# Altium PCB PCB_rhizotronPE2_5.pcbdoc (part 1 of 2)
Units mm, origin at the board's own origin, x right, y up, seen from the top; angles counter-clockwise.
Board outline 129.03 x 83.82 mm, 2 copper layers (Top Layer, Bottom Layer); 83 components, 240 nets, 494 pads, 295 vias.
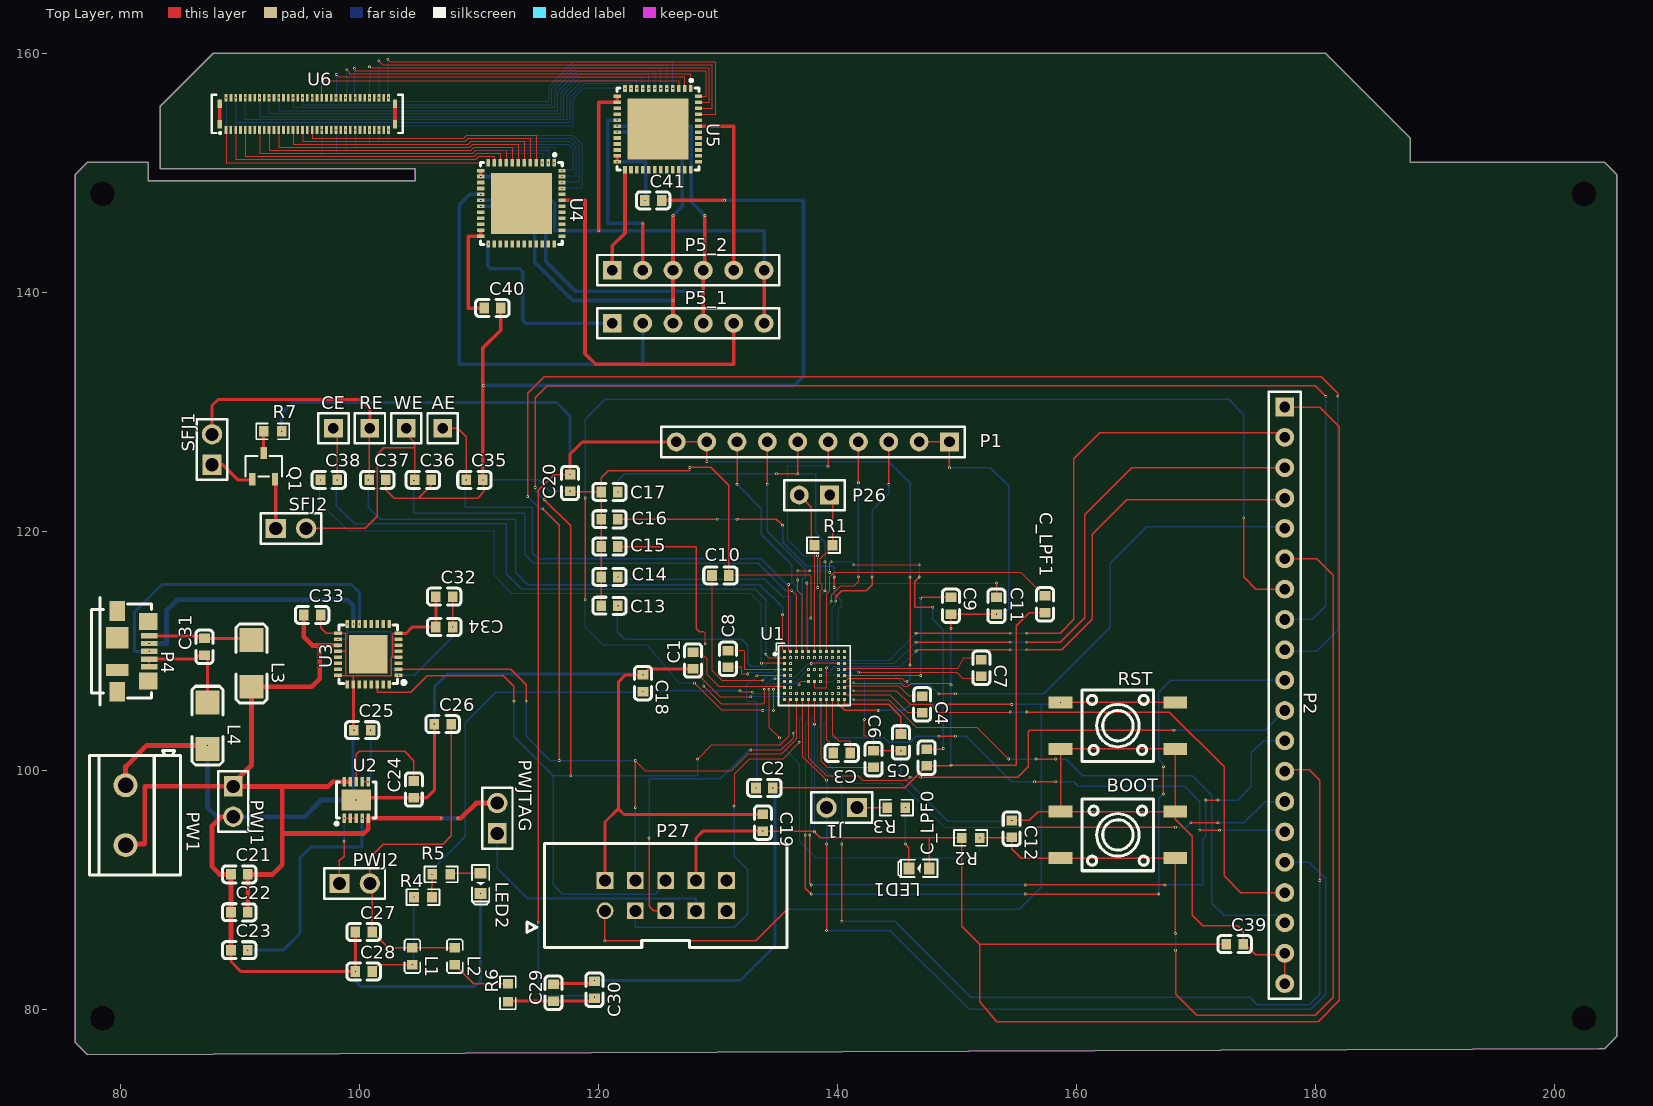
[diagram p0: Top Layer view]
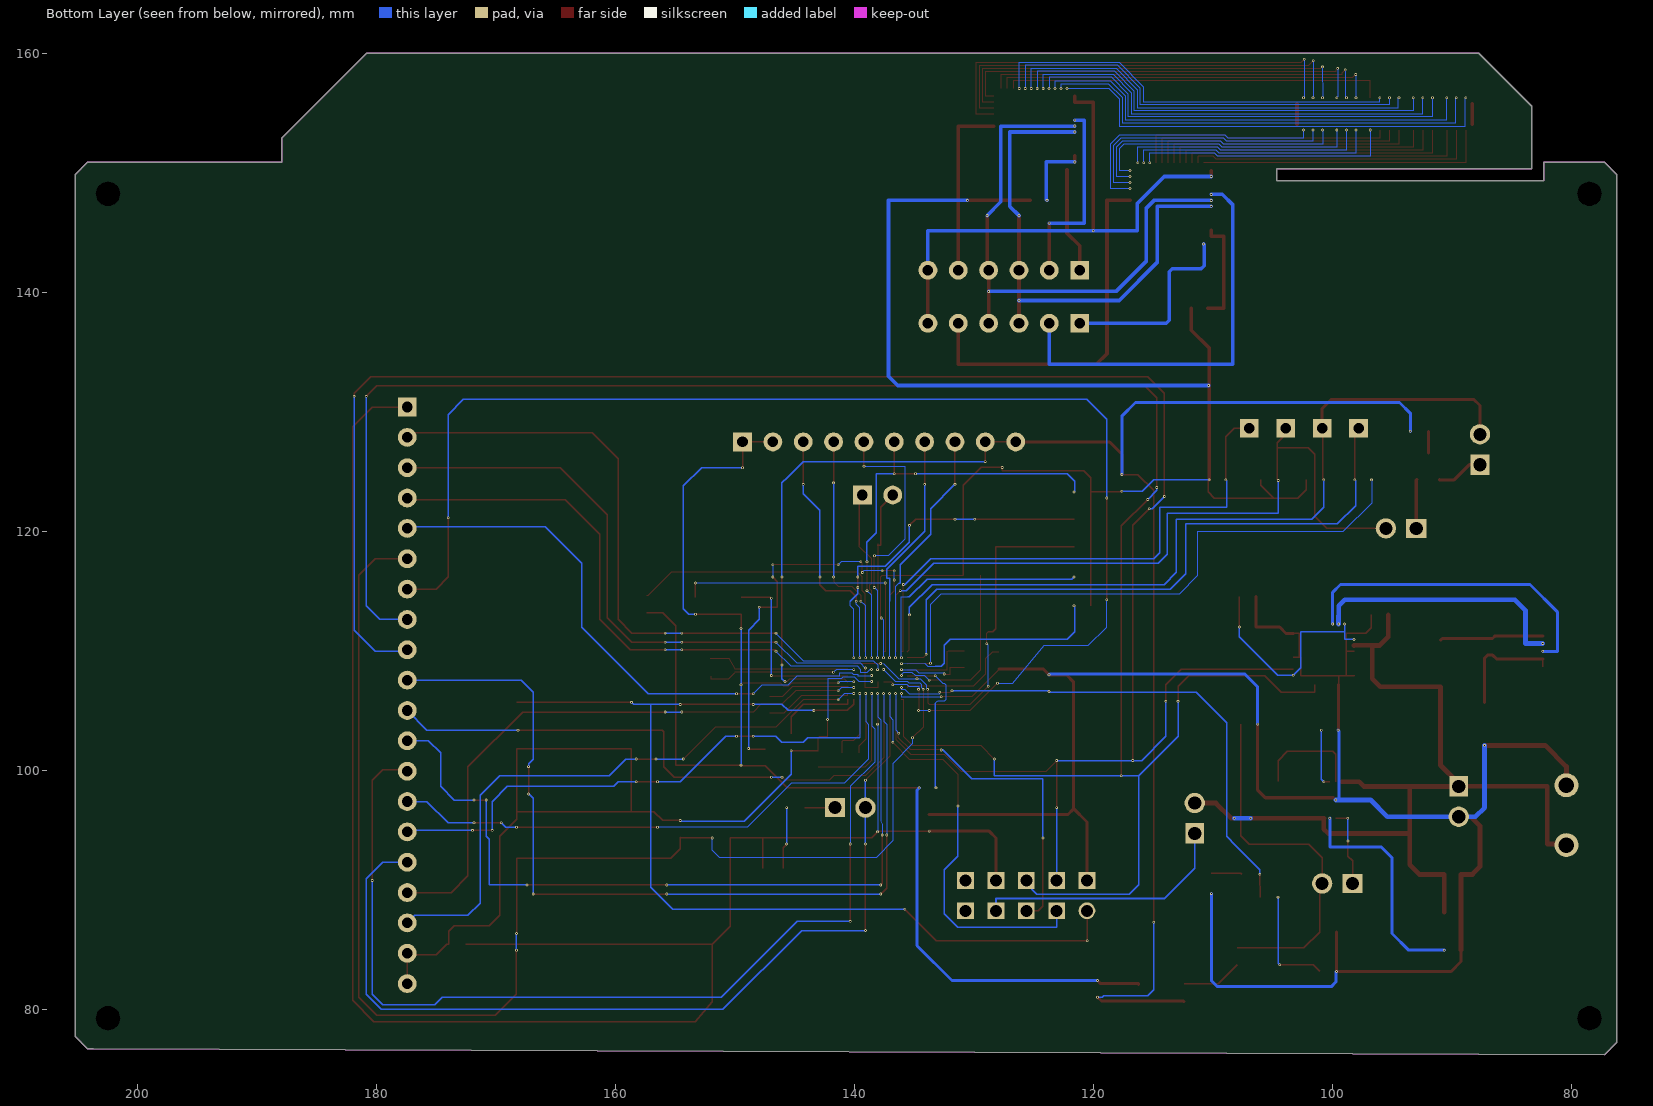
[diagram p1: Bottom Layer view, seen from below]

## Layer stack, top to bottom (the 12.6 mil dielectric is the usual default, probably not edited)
Top Layer: signal copper (thickness not stored)
Dielectric: dielectric 0.32, FR-4, Dk 4.8
Bottom Layer: signal copper (thickness not stored)

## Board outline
82.296,150.876 82.296,149.352 104.648,149.352 104.648,150.368 83.312,150.368 83.312,150.876 83.312,151.242 83.312,151.47 83.312,152.908 83.312,155.575 87.757,160.02 90.424,160.02 180.848,160.02 187.96,152.908 187.96,150.876 204.216,150.876 205.232,149.86 205.232,77.724 204.216,76.708 203.708,76.708 77.216,76.2 76.2,77.216 76.2,149.86 77.216,150.876 82.299,150.876
cut-out: 79.502,79.248 ccw(c78.486,79.248) 77.47,79.248 ccw(c78.486,79.248)
cut-out: 79.502,148.248 ccw(c78.486,148.248) 77.47,148.248 ccw(c78.486,148.248)
cut-out: 203.502,148.248 ccw(c202.486,148.248) 201.47,148.248 ccw(c202.486,148.248)
cut-out: 203.502,79.248 ccw(c202.486,79.248) 201.47,79.248 ccw(c202.486,79.248)

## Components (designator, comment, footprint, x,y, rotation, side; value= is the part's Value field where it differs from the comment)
AE "HDR-M-2.54_1x1" HDR-M-2.54_1X1 106.958,128.627 r270 top
BOOT "K4-6×6_SMD" KEY-SMD_4P-L6.0-W6.0-P3.90-LS10.0 163.473,94.591 r180 top
C1 "0.47uF" C0603 127.913,109.196 r90 top
C2 "0.47uF" C0603 133.882,98.528 r0 top
C3 "0.1uF" C0603 140.359,101.449 r180 top
C4 "0.1uF" C0603 147.09,105.513 r270 top
C5 "0.47uF" C0603 145.312,102.338 r90 top
C6 "0.47uF" C0603 143.026,100.941 r90 top
C7 "0.1uF" C0603 152.043,108.561 r270 top
C8 "0.1uF" C0603 130.834,109.323 r270 top
C9 "0.47uF" C0603 149.503,113.768 r90 top
C10 "0.47uF" C0603 130.199,116.308 r180 top
C11 "4.7uF" C0603 153.313,113.768 r90 top
C12 "0.1uF" C0603 154.583,95.099 r270 top
C13 "0.1uF" C0603 120.928,113.768 r0 top
C14 "0.1uF" C0603 120.928,116.181 r0 top
C15 "0.1uF" C0603 120.928,118.721 r0 top
C16 "0.1uF" C0603 120.928,121.007 r0 top
C17 "0.1uF" C0603 120.928,123.293 r0 top
C18 "0.1uF" C0603 123.722,107.291 r270 top
C19 "0.1uF" C0603 133.755,95.607 r270 top
C20 "0.1uF" C0603 117.626,124.055 r90 top
C21 "0.1uF" C0603 89.94,91.289 r0 top
C22 "10uF" C0603 89.94,88.114 r0 top
C23 "1uF" C0603 89.94,84.939 r0 top
C24 "1uF" C0603 104.545,98.401 r90 top
C25 "1uF" C0603 100.227,103.354 r0 top
C26 "10uF" C0603 106.958,103.862 r0 top
C27 "0.1uF" C0603 100.354,86.463 r0 top
C28 "0.1uF" C0603 100.354,83.161 r0 top
C29 "0.1uF" C0603 116.229,81.383 r90 top
C30 "10uF" C0603 119.658,81.637 r90 top
C31 "0.1uF" C0603 87.019,110.339 r90 top
C32 "0.1uF" C0603 107.085,114.53 r0 top
C33 "0.1uF" C0603 96.036,113.006 r0 top
C34 "0.1uF" C0603 107.085,111.99 r180 top
C35 "0.1uF" C0603 109.625,124.309 r0 top
C36 "0.1uF" C0603 105.307,124.309 r0 top
C37 "0.1uF" C0603 101.497,124.309 r0 top
C38 "0.1uF" C0603 97.433,124.309 r0 top
C39 "0.1uF" C0603 173.252,85.447 r0 top
C40 "0.1uF" C0603 111.125,138.684 r0 top
C41 "0.1uF" C0603 124.587,147.701 r0 top
C_LPF0 "4.7uF" C0603 147.471,101.068 r90 top
C_LPF1 "4.7uF" C0603 157.377,113.895 r90 top
CE "HDR-M-2.54_1x1" HDR-M-2.54_1X1 97.814,128.627 r270 top
J1 "HDR-M-2.54_1x2" HDR-M-2.54_1X2 140.359,96.877 r180 top
L1 "60Ω" L0603 104.418,84.431 r270 top
L2 "60Ω" L0603 107.974,84.431 r270 top
L3 "80Ω" L1806 90.956,108.942 r270 top
L4 "80Ω" L1806 87.273,103.735 r270 top
LED1 "LED-0603_G" LED0603_GREEN 146.836,91.797 r180 top
LED2 "LED-0603_G" LED0603_GREEN 110.133,90.527 r270 top
P1 "HDR-F-2.54_1x10" HDR-F-2.54_1X10 137.946,127.484 r180 top
P2 "HDR-F-2.54_1x20" HDR-F-2.54_1X20 177.443,106.275 r270 top
P4 "Micro B USB 2.0 SMD connector" SD-47346-001 83.082,109.958 r270 top
P5_1 "HDR-F-2.54_1x6" HDR-F-2.54_1X6 126.238,137.414 r0 top
P5_2 "HDR-F-2.54_1x6" HDR-F-2.54_1X6 126.238,141.859 r0 top
P26 "P26" HDR-F-2.54_1X2 138.073,123.039 r180 top
P27 "CONNMOLEX 2X5 Male" JTAG-10PIN-2.54MM-PTH 125.627,89.511 r0 top
PW1 "CONN-TH_2P-P5.00" CONN-TH_2P-P5.00 80.415,96.242 r270 top
PWJ1 "HDR-M-2.54_1x2" HDR-M-2.54_1X2 89.432,97.385 r270 top
PWJ2 "HDR-M-2.54_1x2" HDR-M-2.54_1X2 99.592,90.527 r0 top
PWJTAG "HDR-M-2.54_1x2" HDR-M-2.54_1X2 111.53,95.988 r90 top
Q1 "MMBFJ177" SOT-23-3_L3.0-W1.7-P0.95-LS2.9-BR 91.972,125.452 r270 top
R1 "200" R0603 138.835,118.848 r0 top
R2 "100K" R0603 151.154,94.337 r180 top
R3 "560" R0603 144.931,96.877 r180 top
R4 "2.2" R0603 105.307,89.384 r180 top
R5 "560" R0603 106.831,91.289 r180 top
R6 "2.2" R0603 112.419,81.383 r90 top
R7 "150K" R0603 92.734,128.373 r0 top
RE "HDR-M-2.54_1x1" HDR-M-2.54_1X1 100.862,128.627 r270 top
RST "K4-6×6_SMD" KEY-SMD_4P-L6.0-W6.0-P3.90-LS10.0 163.473,103.735 r0 top
SFJ1 "HDR-M-2.54_1x2" HDR-M-2.54_1X2 87.654,126.849 r90 top
SFJ2 "HDR-M-2.54_1x2" HDR-M-2.54_1X2 94.258,120.245 r0 top
U1 "ADUCM355BCCZ" LGA-72_L6.0-W5.0-TL_ADUCM355BCCZ-RL7 138.073,107.926 r0 top
U2 "ADP7158ACPZ-3.3-R7" LFCSP-10_L3.0-W3.0-P0.50-BL-EP 99.719,97.512 r0 top
U3 "FT232RQ" QFN-32_L5.0-W5.0-P0.50-BL-EP 100.735,109.704 r90 top
U4 "ADG731BCPZ" LFCSP-48_L7.0-W7.0-P0.50-TL-EP5.1 113.538,147.447 r270 top
U5 "ADG731BCPZ" LFCSP-48_L7.0-W7.0-P0.50-TL-EP5.1 124.968,153.67 r270 top
U6 "DF40GB-70DP-0.4V(51)" "HIROSE DF40GB-70DP-0.4V(51)" 95.631,154.94 r0 top
WE "HDR-M-2.54_1x1" HDR-M-2.54_1X1 103.91,128.627 r270 top

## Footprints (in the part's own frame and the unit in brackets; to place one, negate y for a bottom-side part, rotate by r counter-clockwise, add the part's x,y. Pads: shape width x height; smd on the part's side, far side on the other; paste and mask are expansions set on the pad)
C0603 [mm]
  rect 0.8x0.9 smd paste+0 mask+0.051: 1(-0.7,0) 2(0.7,0)
  silkscreen extent -1.41,-0.71 1.39,0.72
CONN-TH_2P-P5.00 [mm]
  round 2 hole 1.3 paste+0 mask+0.051: 1(-2.504,0) 2(2.504,0)
  silkscreen extent -5.4,-3 5,4.6
HDR-F-2.54_1X2 [mil]
  rect 62x62 hole 35 paste+0 mask+2: 1(-50,0)
  round 62 hole 35 paste+0 mask+2: 2(50,0)
  silkscreen extent -100,-49 100,50
HDR-F-2.54_1X6 [mil]
  rect 62x62 hole 35 paste+0 mask+2: 1(-200,0)
  round 62 hole 35 paste+0 mask+2: 2(-100,0) 3(0,0) 4(100,0) 5(200,0) 6(300,0)
  silkscreen extent -250,-50 350,50
HDR-F-2.54_1X10 [mil]
  rect 62x62 hole 35 paste+0 mask+2: 1(-450,0)
  round 62 hole 35 paste+0 mask+2: 2(-350,0) 3(-250,0) 4(-150,0) 5(-50,0) 6(50,0) 7(150,0) 8(250,0) 9(350,0) 10(450,0)
  silkscreen extent -500,-50 500,50
HDR-F-2.54_1X20 [mil]
  rect 62x62 hole 35 paste+0 mask+2: 1(-950,0)
  round 62 hole 35 paste+0 mask+2: 2(-850,0) 3(-750,0) 4(-650,0) 5(-550,0) 6(-450,0) 7(-350,0) 8(-250,0) 9(-150,0) 10(-50,0) 11(50,0) 12(150,0) 13(250,0) 14(350,0) 15(450,0) 16(550,0) 17(650,0) 18(750,0) 19(850,0) 20(950,0)
  silkscreen extent -1000,-53 1000,53
HDR-M-2.54_1X1 [mil]
  rect 62x62 hole 35 paste+0 mask+2: 1(0,0)
  silkscreen extent -50,-50 50,50
HDR-M-2.54_1X2 [mm]
  rect 1.7x1.575 hole 1.1 paste+0 mask+0.051: 1(-1.27,0)
  round 1.7 hole 1.1 paste+0 mask+0.051: 2(1.27,0)
  silkscreen extent -2.54,-1.27 2.54,1.27
"HIROSE DF40GB-70DP-0.4V(51)" [mm]
  rect 0.23x0.66 smd paste+0 mask+0.051: 1(-6.8,-1.355) 2(-6.8,1.355) 3(-6.401,-1.355) 4(-6.4,1.355) 5(-6,-1.355) 6(-6,1.355) 7(-5.6,-1.355) 8(-5.6,1.355) 9(-5.2,-1.355) 10(-5.2,1.355) 11(-4.8,-1.355) 12(-4.8,1.355) 13(-4.4,-1.355) 14(-4.4,1.355) 15(-4,-1.355) 16(-4,1.355) 17(-3.6,-1.355) 18(-3.6,1.355) 19(-3.2,-1.355) 20(-3.2,1.355) 21(-2.8,-1.355) 22(-2.8,1.355) 23(-2.4,-1.355) 24(-2.4,1.355) 25(-2,-1.355) 26(-2,1.355) 27(-1.6,-1.355) 28(-1.6,1.355) 29(-1.2,-1.355) 30(-1.2,1.355) 31(-0.8,-1.355) 32(-0.8,1.355) 33(-0.4,-1.355) 34(-0.4,1.355) 35(0,-1.355) 36(0,1.355) 37(0.4,-1.355) 38(0.4,1.355) 39(0.8,-1.355) 40(0.8,1.355) 41(1.2,-1.355) 42(1.2,1.355) 43(1.6,-1.355) 44(1.6,1.355) 45(2,-1.355) 46(2,1.355) 47(2.4,-1.355) 48(2.4,1.355) 49(2.8,-1.355) 50(2.8,1.355) 51(3.2,-1.355) 52(3.2,1.355) 53(3.6,-1.355) 54(3.6,1.355) 55(4,-1.355) 56(4,1.355) 57(4.4,-1.355) 58(4.4,1.355) 59(4.8,-1.355) 60(4.8,1.355) 61(5.2,-1.355) 62(5.2,1.355) 63(5.6,-1.355) 64(5.6,1.355) 65(6,-1.355) 66(6,1.355) 67(6.4,-1.355) 68(6.4,1.355) 69(6.8,-1.355) 70(6.8,1.355)
  rect 0.35x0.7 smd paste+0 mask+0.051: 71(7.335,-0.86) 72(7.335,0.86) 73(-7.335,-0.86) SHLD(-7.335,0.86)
  silkscreen extent -8,-1.7 8,1.6
JTAG-10PIN-2.54MM-PTH [mm]
  round 1.4 hole 1.001 paste+0 mask+0.051: 1(-5.08,-1.27)
  rect 1.4x1.4 hole 1.001 paste+0 mask+0.051: 2(-5.08,1.27) 3(-2.54,-1.27) 4(-2.54,1.27) 5(0,-1.27) 6(0,1.27) 7(2.54,-1.27) 8(2.54,1.27) 9(5.08,-1.27) 10(5.08,1.27)
  silkscreen extent -11.61,-4.34 10.13,4.34
KEY-SMD_4P-L6.0-W6.0-P3.90-LS10.0 [mm]
  rect 2x1 smd paste+0 mask+0.051: 1(-4.8,1.95) 2(4.8,1.95) 3(-4.8,-1.95) 4(4.8,-1.95)
  silkscreen extent -3,-3 3,3
L0603 [mm]
  rect 0.8x0.864 smd paste-100 mask+0.051: 1(-0.7,0) 2(0.7,0)
  silkscreen extent -1.42,-0.65 1.41,0.67
L1806 [mm]
  rect 2x2 smd paste+0 mask+0.051: 1(-1.95,0) 2(1.95,0)
  silkscreen extent -3.3,-1.3 3.3,1.3
LED0603_GREEN [mm]
  rect 0.9x1 smd paste+0 mask+0.051: 1(-0.85,0) 2(0.85,0)
  silkscreen extent -1.54,-0.73 1.75,0.73
LFCSP-10_L3.0-W3.0-P0.50-BL-EP [mm]
  rect 0.3x0.8 smd paste+0 mask+0.051: 1(-1,-1.524) 2(-0.5,-1.524) 3(0,-1.524) 4(0.5,-1.524) 5(1,-1.524) 6(1,1.524) 7(0.5,1.524) 8(0,1.524) 9(-0.5,1.524) 10(-1,1.524)
  rect 2.5x1.75 smd paste+0 mask+0.051: 11(0,0)
  silkscreen extent -1.77,-2.11 1.65,1.52
LFCSP-48_L7.0-W7.0-P0.50-TL-EP5.1 [mm]
  rect 0.6x0.3 smd paste-100 mask+0.051: 1(-3.4,2.75) 2(-3.4,2.25) 3(-3.4,1.75) 4(-3.4,1.25) 5(-3.4,0.75) 6(-3.4,0.25) 7(-3.4,-0.25) 8(-3.4,-0.75) 9(-3.4,-1.25) 10(-3.4,-1.75) 11(-3.4,-2.25) 12(-3.4,-2.75) 25(3.4,-2.75) 26(3.4,-2.25) 27(3.4,-1.75) 28(3.4,-1.25) 29(3.4,-0.75) 30(3.4,-0.25) 31(3.4,0.25) 32(3.4,0.75) 33(3.4,1.25) 34(3.4,1.75) 35(3.4,2.25) 36(3.4,2.75)
  rect 0.3x0.6 smd paste-100 mask+0.051: 13(-2.75,-3.4) 14(-2.25,-3.4) 15(-1.75,-3.4) 16(-1.25,-3.4) 17(-0.75,-3.4) 18(-0.25,-3.4) 19(0.25,-3.4) 20(0.75,-3.4) 21(1.25,-3.4) 22(1.75,-3.4) 23(2.25,-3.4) 24(2.75,-3.4) 37(2.75,3.4) 38(2.25,3.4) 39(1.75,3.4) 40(1.25,3.4) 41(0.75,3.4) 42(0.25,3.4) 43(-0.25,3.4) 44(-0.75,3.4) 45(-1.25,3.4) 46(-1.75,3.4) 47(-2.25,3.4) 48(-2.75,3.4)
  rect 5.1x5.1 smd paste-100 mask+0.051: 49(0,0)
  silkscreen extent -4.19,-3.43 3.43,3.43
LGA-72_L6.0-W5.0-TL_ADUCM355BCCZ-RL7 [mm]
  rect 0.25x0.25 smd paste+0 mask+0.051: A1(-2.5,2) A2(-2,2) A3(-1.5,2) A4(-1,2) A5(-0.5,2) A6(0,2) A7(0.5,2) A8(1,2) A9(1.5,2) A10(2,2) A11(2.5,2) B1(-2.5,1.5) B2(-2,1.5) B3(-1.5,1.5) B4(-1,1.5) B5(-0.5,1.5) B6(0,1.5) B7(0.5,1.5) B8(1,1.5) B9(1.5,1.5) B10(2,1.5) B11(2.5,1.5) C1(-2.5,1) C2(-2,1) C10(2,1) C11(2.5,1) D1(-2.5,0.5) D2(-2,0.5) D5(-0.5,0.5) D6(0,0.5) D7(0.5,0.5) D10(2,0.5) D11(2.5,0.5) E1(-2.5,0) E2(-2,0) E5(-0.5,0) E7(0.5,0) E10(2,0) E11(2.5,0) F1(-2.5,-0.5) F2(-2,-0.5) F5(-0.5,-0.5) F6(0,-0.5) F7(0.5,-0.5) F10(2,-0.5) F11(2.5,-0.5) G1(-2.5,-1) G2(-2,-1) G10(2,-1) G11(2.5,-1) H1(-2.5,-1.5) H2(-2,-1.5) H3(-1.5,-1.5) H4(-1,-1.5) H5(-0.5,-1.5) H6(0,-1.5) H7(0.5,-1.5) H8(1,-1.5) H9(1.5,-1.5) H10(2,-1.5) H11(2.5,-1.5) J1(-2.5,-2) J2(-2,-2) J3(-1.5,-2) J4(-1,-2) J5(-0.5,-2) J6(0,-2) J7(0.5,-2) J8(1,-2) J9(1.5,-2) J10(2,-2) J11(2.5,-2)
  silkscreen extent -3.4,-2.5 3,2.7
QFN-32_L5.0-W5.0-P0.50-BL-EP [mil]
  rect 11.8x26 smd paste-3937 mask+1.97: 1(-68.9,-100) 2(-49.21,-100) 3(-29.53,-100) 4(-9.84,-100) 5(9.84,-100) 6(29.53,-100) 7(49.21,-100) 8(68.9,-100) 17(68.9,100) 18(49.21,100) 19(29.53,100) 20(9.84,100) 21(-9.84,100) 22(-29.53,100) 23(-49.21,100) 24(-68.9,100)
  rect 26x11.8 smd paste-3937 mask+1.97: 9(100,-68.9) 10(100,-49.21) 11(100,-29.53) 12(100,-9.84) 13(100,9.84) 14(100,29.53) 15(100,49.21) 16(100,68.9) 25(-100,68.9) 26(-100,49.21) 27(-100,29.53) 28(-100,9.84) 29(-100,-9.84) 30(-100,-29.53) 31(-100,-49.21) 32(-100,-68.9)
  rect 126x126 smd paste-3937 mask+1.97: 33(0,0)
  silkscreen extent -99,-123 96,96
R0603 [mm]
  rect 0.806x0.864 smd paste-100 mask+0.051: 1(-0.753,0) 2(0.753,0)
  silkscreen extent -1.39,-0.66 1.39,0.66
SD-47346-001 [mm]
  rect 0.45x1.38 smd paste+0 mask+0.102: 1(-1.3,-0.69) 2(-0.65,-0.69) 3(0,-0.69) 4(0.65,-0.69) 5(1.3,-0.69)
  rect 1.425x1.55 smd paste+0 mask+0.102: 6(-2.488,-0.775) GND(2.488,-0.775)
  rect 1.65x1.3 smd paste+0 mask+0.102: 7(-3.375,-3.35) 10(3.375,-3.35)
  rect 1.8x1.9 smd paste+0 mask+0.102: 8(-1.15,-3.35)
  rect 1x1.9 smd paste+0 mask+0.102: 9(1.55,-3.35)
  silkscreen extent -4.49,-5.5 4.49,-0.5
SOT-23-3_L3.0-W1.7-P0.95-LS2.9-BR [mm]
  rect 1.037x0.532 smd paste+0 mask+0.051: 1(1.101,-0.95) 2(1.101,0.95) 3(-1.101,0)
  silkscreen extent -0.86,-1.53 0.86,1.53

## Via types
v1: diameter 0.225, hole 0.1, Top Layer to Bottom Layer, tented both sides, 295 vias

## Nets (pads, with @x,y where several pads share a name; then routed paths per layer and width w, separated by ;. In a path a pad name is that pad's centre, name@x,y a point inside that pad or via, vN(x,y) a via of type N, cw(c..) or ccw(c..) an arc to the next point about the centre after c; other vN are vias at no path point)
3V3VOUT: C32.2 C34.1 U3.1 U3.16 U3.18 | length 18.8
  Top Layer w0.125: C34.1@107.785,111.99 C32.2@107.785,114.53
  Bottom Layer w0.125: v1(98.195,110.954) 98.957,110.954 98.957,112.216 v1@98.985,112.244 ; 98.957,111.584 102.64,111.584 102.64,108.589 103.275,107.954 104.573,107.954 107.786,111.167 v1@107.786,111.99
  other v1: 103.275,107.954 107.785,111.99 98.985,112.244
5VUSB: C21.2 C22.2 C33.1 L3.2 PW1.2 PWJ1.1 PWJTAG.2 U2.5 U2.9 U2.10 U3.19 | length 79.4
  Top Layer w0.4: PW1.2@80.415,93.737 80.506,93.829 82.03,93.829 82.03,98.655 ; 82.066,98.655 82.03,98.655 ; PWJ1.1@89.432,98.655 97.384,98.654 97.765,99.035 U2.10@98.719,99.036 ; C22.2@90.64,88.114 C21.2@90.64,91.289 92.734,91.289 93.537,92.092 93.537,98.655 ; L3.2@90.956,106.991 95.99,106.991 96.671,107.672 96.671,109.958 96.671,110.466 U3.19@98.195,110.453 ; L3.2@90.956,106.992 90.956,100.433 89.432,98.909 PWJ1.1@89.432,98.655 82.03,98.655 ; 93.536,94.464 93.536,94.718 100.354,94.718 100.72,95.084 U2.5@100.719,95.988 ; C33.1@95.335,113.006 95.335,111.162 96.046,110.453 96.671,110.453 ; U2.10@98.719,99.036 U2.9@99.219,99.036 ; U2.5@100.719,95.988 v1@106.831,95.988 ; v1@108.228,95.988 108.482,95.988 109.752,97.258 PWJTAG.2@111.53,97.258
  Bottom Layer w0.4: v1@106.831,95.988 v1@108.228,95.988
  other v1: 106.831,95.988 108.228,95.988
AFEDIE_GPIO0: P2.17 U1.G10 | length 49.8
  Top Layer w0.1: v1(141.375,106.656) 144.931,106.656 146.074,105.513 147.852,105.513 148.487,104.878 v1@154.456,104.878
  Top Layer w0.125: v1@155.853,104.878 167.791,104.878 172.363,100.306 172.363,91.162 173.76,89.765 P2.17@177.443,89.765
  Bottom Layer w0.1: v1(140.073,106.926) 141.104,106.926 v1(141.375,106.656)
  Bottom Layer w0.125: v1@154.456,104.878 v1@155.853,104.878
  other v1: 154.456,104.878 155.853,104.878
AFEDIE_GPIO1: P2.18 U1.H10 | length 50.6
  Top Layer w0.1: v1(141.375,105.894) 144.296,105.894 146.582,103.608 151.662,103.608 v1@154.329,100.941
  Top Layer w0.125: v1@156.615,100.941 v1@158.266,100.941
  Bottom Layer w0.1: v1(140.073,106.426) 140.842,106.426 v1(141.375,105.894)
  Bottom Layer w0.125: v1@154.329,100.941 v1@156.615,100.941 ; v1@158.266,100.941 159.155,100.941 160.552,99.544 169.696,99.544 171.347,97.893 171.347,88.876 172.363,87.86 176.808,87.86 P2.18@177.443,87.225
  other v1: 154.329,100.941 156.615,100.941 158.266,100.941
AGND: C2.2 C9.1 C10.1 C11.1 C13.1 C14.1 C15.1 C16.1 C17.1 C20.1 C29.2 C30.2 C35.2 C36.2 C37.2 C40.2 C41.2 C_LPF0.1 C_LPF1.1 P1.1 P1.2 U1.B5 U1.F10 | length 252.5
  Top Layer w0.1: C10.1@130.899,116.308 137.692,116.308 137.819,116.181 137.819,112.81 v1@137.76,112.752 ; v1@141.375,107.291 145.312,107.291 145.566,107.037 145.926,107.037 146.18,107.291 149.503,107.291 v1@149.503,107.164
  Top Layer w0.125: C37.2@102.197,124.309 102.197,123.482 102.894,122.785 104.926,122.785 ; C36.2@106.007,124.309 106.007,123.866 104.926,122.785 ; C35.2@110.325,124.309 110.387,124.309 110.387,123.293 109.879,122.785 104.926,122.785 ; v1(117.626,123.355) 117.688,123.293 C17.1@120.228,123.293 ; C13.1@120.228,113.768 C14.1@120.228,116.181 C15.1@120.228,118.721 C16.1@120.228,121.007 C17.1@120.228,123.293 ; C10.1@130.899,116.308 130.899,123.863 129.413,125.349 v1(127.635,125.349) 127.635,125.071 120.801,125.071 120.228,124.498 C17.1@120.228,123.293 ; C2.2@134.582,98.528 145.631,98.528 C_LPF0.1@147.471,100.368 149.438,100.368 149.503,100.433 154.964,100.433 154.964,112.117 156.042,113.195 C_LPF1.1@157.377,113.195 ; P1.2@146.836,127.484 P1.1@149.376,127.484 v1@149.376,125.325 ; v1(149.503,111.863) C9.1@149.503,113.068 v1(153.313,113.068)
  Top Layer w0.254: C29.2@116.229,82.083 116.229,82.145 119.404,82.145 C30.2@119.658,82.399
  Top Layer w0.3: C35.2@110.325,124.309 110.325,135.344 111.825,136.844 C40.2@111.825,138.684 ; C41.2@125.287,147.701 v1(130.556,147.701)
  Bottom Layer w0.1: v1(137.573,109.426) 137.573,112.563 v1(137.762,112.752) ; v1@140.073,107.426 141.239,107.426 v1@141.375,107.291
  Bottom Layer w0.125: v1@110.325,124.309 114.959,124.309 115.913,123.355 v1(117.626,123.355) ; v1@149.376,125.325 152.805,125.325 154.329,123.801 154.329,113.514 153.883,113.068 v1(153.313,113.068) ; v1@149.503,100.433 149.503,107.164 v1(149.503,111.863)
  Bottom Layer w0.254: v1@119.658,82.399 131.85,82.399 134.771,85.32 134.771,98.339 v1@134.582,98.528
  Bottom Layer w0.3: v1(110.363,132.207) 136.398,132.207 137.16,132.969 137.16,147.701 132.334,147.701 v1(130.556,147.701)
  other v1: 119.658,82.399 134.582,98.528 149.503,100.433 149.503,107.164 141.375,107.321 140.073,107.416 110.325,124.309 149.376,125.325
AIN0: P1.3 U1.B9 | length 21.2
  Top Layer w0.125: v1@139.851,114.149 139.851,114.53 140.359,115.038 142.391,115.038 142.899,115.546 v1@142.899,116.181 ; v1@144.296,123.928 P1.3@144.296,127.484
  Bottom Layer w0.1: v1(139.573,109.426) 139.573,113.617 139.851,113.895 v1@139.851,114.149
  Bottom Layer w0.125: v1@142.899,116.181 142.899,121.769 144.296,123.166 v1@144.296,123.928
  other v1: 139.851,114.149 142.899,116.181 144.296,123.928
AIN1: P1.4 U1.B8 | length 19.8
  Top Layer w0.1: v1@139.47,114.149 139.47,114.657 140.232,115.419 141.375,115.419 141.756,115.8 v1@141.756,116.181
  Top Layer w0.125: v1@141.756,124.055 P1.4@141.756,127.484
  Bottom Layer w0.1: v1(139.073,109.426) 139.073,113.752 v1@139.47,114.149
  Bottom Layer w0.125: v1@141.756,116.181 v1@141.756,124.055
  other v1: 139.47,114.149 141.756,116.181 141.756,124.055
AIN2: P1.5 U1.B6 | length 23.3
  Top Layer w0.1: v1@138.334,117.959 v1(138.347,115.292)
  Top Layer w0.125: v1@139.216,125.452 P1.5@139.216,127.484
  Bottom Layer w0.1: v1(138.073,109.426) 138.073,115.038 v1@138.327,115.292 ; v1@138.327,117.959 137.184,117.959 135.787,119.356 135.787,120.224 135.787,125.452 v1@139.216,125.452
  other v1: 138.336,117.959 139.216,125.452
AIN3: C17.2 P1.6 U1.B7 | length 36.4
  Top Layer w0.1: v1(138.962,115.038) v1(138.962,117.451)
  Top Layer w0.125: v1@134.898,124.817 136.676,124.817 P1.6@136.676,127.484
  Bottom Layer w0.1: v1(138.573,109.426) 138.573,114.649 v1(138.962,115.038)
  Bottom Layer w0.125: v1@121.629,123.293 121.563,123.293 121.563,124.182 122.198,124.817 v1@134.898,124.817 ; v1@136.676,124.817 138.2,124.817 138.2,119.864 138.962,119.102 v1(138.962,117.451)
  other v1: 121.628,123.293 134.898,124.817 136.676,124.817
AIN5: P1.7 U1.B4 | length 19.6
  Top Layer w0.125: v1@134.136,123.928 P1.7@134.136,127.484
  Bottom Layer w0.1: v1@137.072,109.427 137.072,114.149
  Bottom Layer w0.125: v1@134.136,123.928 134.136,119.991 137.311,116.816 137.311,116.054 137.057,116.054 137.057,114.149
  other v1: 137.073,109.426 134.136,123.928
AIN6: P1.8 U1.B3 | length 20.2
  Top Layer w0.125: v1@131.596,123.928 P1.8@131.596,127.484
  Bottom Layer w0.1: 136.295,115.673 136.573,115.395 v1(136.573,109.426)
  Bottom Layer w0.125: v1@131.596,123.928 133.628,121.896 133.628,119.737 136.168,117.197 136.168,115.673 136.295,115.673
  other v1: 131.596,123.928
AVDD: C20.2 C29.1 C30.1 P1.9 P1.10 R6.1 R7.2 U1.F11 | length 144
  Top Layer w0.1: U1.F11@140.573,107.426 140.621,107.426 140.867,107.672 145.439,107.672 145.683,107.427 v1(145.82,107.427)
  Top Layer w0.125: v1@114.959,87.225 114.959,123.42 116.294,124.755 v1(117.626,124.755) ; P1.10@126.516,127.484 P1.9@129.056,127.484 v1@129.056,125.833 ; v1@146.074,108.815 v1@146.074,116.181
  Top Layer w0.254: R6.1@112.419,80.629 112.472,80.683 C29.1@116.229,80.683 119.339,80.683 C30.1@119.658,81.002 ; v1(117.626,124.755) 117.626,126.468 118.642,127.484 P1.10@126.516,127.484
  Bottom Layer w0.125: v1(114.959,87.276) 114.959,81.637 115.467,81.129 119.15,81.129 119.277,81.002 v1@119.658,81.002 ; v1@129.056,125.833 144.296,125.833 145.604,124.525 146.074,124.055 v1@146.074,116.181 ; v1@145.82,107.418 146.074,107.672 v1@146.074,108.815
  Bottom Layer w0.254: v1@93.487,128.373 93.487,129.888 94.385,130.786 116.483,130.786 117.626,129.643 v1(117.626,124.755)
  other v1: 119.658,81.002 146.074,108.815 146.074,116.181 129.056,125.833 93.487,128.373
C23_2: C23.2 U2.4 | length 19.3
  Bottom Layer w0.254: v1@90.641,84.939 93.623,84.939 95.02,86.336 95.02,92.686 95.909,93.575 100.219,93.575 v1@100.219,95.988
  other v1: 90.64,84.939 100.219,95.988
C24_2: C24.2 U2.8 | length 9.2
  Top Layer w0.125: U2.8@99.719,99.036 99.719,101.322 99.973,101.576 103.783,101.576 104.545,100.814 C24.2@104.545,99.101
C25_2: C25.2 U2.6 U2.7 | length 4.9
  Top Layer w0.125: U2.7@100.219,99.036 U2.6@100.719,99.036
  Bottom Layer w0.125: v1@100.719,99.036 100.927,99.244 v1@100.927,103.354
  other v1: 100.719,99.036 100.927,103.354
CAP_POT0: C38.1 U1.C1 | length 51.5
  Top Layer w0.1: v1@133.628,108.942 135.557,108.942 U1.C1@135.573,108.926
  Bottom Layer w0.1: v1@96.733,124.309 96.671,124.247 96.671,122.404 99.084,119.991 111.276,119.991 111.276,116.308 112.8,114.784 132.739,114.784 133.628,113.895 v1@133.628,108.942
  other v1: 133.638,108.951 96.733,124.309
CAP_POT1: U1.C11
CE0: C38.2 CE.1 U1.B1 | length 54.6
  Top Layer w0.1: v1(134.009,109.704) 134.263,109.427 U1.B1@135.573,109.426
  Top Layer w0.125: CE.1@97.814,128.627 98.133,128.308 C38.2@98.133,124.309
  Bottom Layer w0.125: v1@98.133,124.309 98.068,124.244 98.068,122.15 99.592,120.626 112.292,120.626 112.292,116.435 113.562,115.165 133.12,115.165 134.009,114.276 v1(134.009,109.704)
  other v1: 98.133,124.309
CE1: U1.B11
D1: P5_1.5 U4.43 | length 31
  Top Layer w0.3: U4.43@116.938,147.697 118.872,147.697 118.872,134.874 119.761,133.985 131.318,133.985 P5_1.5@131.318,137.414
D2: P5_2.5 U5.43 | length 15
  Top Layer w0.3: U5.43@128.368,153.92 131.318,153.92 P5_2.5@131.318,141.859
DE0: AE.1 C35.1 U1.A2 | length 45.9
  Top Layer w0.1: 135.904,109.958 135.904,114.734 ; 135.904,114.736 v1@135.904,115.546 ; 135.914,109.958 U1.A2@136.041,109.958
  Top Layer w0.125: AE.1@106.958,128.627 108.225,128.627 108.924,127.926 C35.1@108.924,124.309
  Bottom Layer w0.125: v1@108.924,124.309 108.863,124.248 108.863,122.023 114.451,122.023 114.451,118.213 114.959,117.705 133.628,117.705 135.787,115.546 v1@135.914,115.546
  other v1: 135.914,115.546 108.924,124.309
DE1: U1.A10
DIN: P5_1.4 P5_2.4 U4.18 U5.18 | length 47.6
  Top Layer w0.3: P5_1.4@128.778,137.414 P5_2.4@128.778,141.859 128.905,141.986 v1(128.905,146.431)
  Bottom Layer w0.3: v1(110.138,147.697) 114.939,147.697 115.57,147.066 115.57,142.621 118.11,140.081 v1(128.778,140.081) ; v1(121.568,153.92) 127.762,153.92 127.762,147.574 v1(128.905,146.431)
DVDD: C18.2 C19.2 C39.1 LED1.1 P2.1 P27.8 R2.2 R4.1 R5.2 U1.F1 U1.G2 U1.J6 | length 204.3
  Top Layer w0.1: v1(131.85,106.656) 131.977,106.529 v1(132.866,106.529) ; v1@138.073,103.862 U1.J6@138.073,105.926
  Top Layer w0.125: R4.1@106.06,89.384 R5.2@106.076,91.289 ; v1(133.755,94.907) 138.011,94.907 138.073,94.845 138.581,94.337 R2.2@150.4,94.337 150.4,86.962 151.916,85.447 ; LED1.1@147.686,91.797 147.686,94.337 ; C39.1@172.552,85.447 151.916,85.447 ; P2.1@177.443,130.405 180.364,130.405 182.015,128.754 182.015,80.748 180.237,78.97 153.313,78.97 151.916,80.621 151.916,85.447
  Top Layer w0.254: P27.8@128.167,90.781 128.167,94.337 128.737,94.907 v1(133.755,94.907)
  Bottom Layer w0.1: v1(132.866,106.529) 132.866,106.402 135.406,106.402 135.787,106.783 136.074,106.783 v1@136.074,106.925 ; v1@138.073,94.845 v1@138.073,103.862
  Bottom Layer w0.125: v1@106.076,91.289 106.076,91.677 108.101,93.702 108.863,94.464 108.863,103.989 111.403,106.529 123.661,106.529 v1@123.722,106.59 ; v1(123.722,106.591) 123.787,106.656 v1(131.85,106.656)
  other v1: 106.076,91.289 138.073,94.845 138.082,103.862 136.073,106.926
GND: BOOT.3 BOOT.4 C1.1 C5.1 C6.2 C12.1 C18.1 C19.1 C21.1 C22.1 C23.1 C24.1 C25.1 C26.1 C27.1 C28.1 C32.1 C33.2 C34.2 C39.2 L4.2 LED2.2 P2.19 P2.20 P27.2 PW1.1 PWJ1.2 RST.3 RST.4 U1.F2 U1.F7 U1.H2 U2.11 U3.4 U3.8 U3.17 U3.20 U3.24 U3.26 | length 269.2
  Top Layer w0.1: C1.1@127.913,108.496 127.913,108.434 130.199,106.148 v1(132.739,106.148) ; v1@142.264,104.243 142.264,102.846 142.899,102.846 143.026,102.719 C6.2@143.026,101.641
  Top Layer w0.125: C33.2@96.736,113.006 96.736,111.925 97.207,111.454 U3.17@98.195,111.454 98.83,111.454 98.83,109.953 ; U3.24@98.195,107.954 98.195,107.926 98.83,107.926 ; U3.20@98.195,109.953 98.825,109.953 98.83,107.926 ; 98.83,107.987 98.83,107.926 ; U3.26@99.485,107.164 99.485,107.926 ; 102.767,109.454 102.767,111.454 U3.8@103.275,111.454 ; U3.4@103.275,109.454 102.64,109.454 102.64,107.926 99.485,107.926 ; C6.2@143.026,101.641 v1(145.309,101.641) C5.1@145.312,101.638 ; v1(154.583,95.799) 156.045,95.799 156.787,96.541 BOOT.4@158.673,96.541 ; BOOT.3@168.273,96.541 168.273,95.886 169.696,94.464 169.696,87.86 170.585,86.971 173.508,86.971 173.953,86.529 C39.2@173.952,85.447 ; C39.2@173.952,85.447 174.141,85.447 175.03,84.558 177.316,84.558 P2.19@177.443,84.685 P2.20@177.443,82.145 ; 98.83,107.926 99.485,107.926 ; BOOT.4@158.673,96.541 RST.3@158.673,101.785 RST.4@168.273,101.785 BOOT.3@168.273,96.541 BOOT.4@158.673,96.541
  Top Layer w0.254: C23.1@89.239,84.939 89.239,83.989 90.067,83.161 C28.1@99.653,83.161 ; U3.26@99.485,107.164 99.485,103.354 C25.1@99.526,103.354 ; C28.1@99.654,83.161 C27.1@99.654,86.463 ; U2.11@99.719,97.512 99.908,97.701 C24.1@104.545,97.701 105.623,97.701 106.258,98.336 C26.1@106.258,103.862 ; U3.8@103.275,111.454 103.882,111.454 104.418,111.99 C34.2@106.385,111.99 C32.1@106.385,114.53 ; P27.2@120.547,90.781 120.547,95.676 121.69,96.819 ; C18.1@123.722,107.991 124.227,108.496 C1.1@127.913,108.496 ; C18.1@123.722,107.991 122.264,107.992 121.69,107.418 121.69,96.75 122.132,96.308 C19.1@133.755,96.307
  Top Layer w0.4: PW1.1@80.415,98.746 80.415,100.306 82.193,102.084 L4.2@87.273,102.084 ; C23.1@89.24,84.939 C22.1@89.24,88.114 C21.1@89.24,91.289 88.289,91.289 87.654,91.924 87.654,95.353 88.416,96.115 PWJ1.2@89.432,96.115
  Bottom Layer w0.1: v1(132.739,106.148) 136.073,106.148 v1(136.073,106.426) ; v1(138.573,107.426) 139.605,107.426 139.978,107.799 140.994,107.799 141.121,107.672 142.264,107.672 v1@142.264,104.243
  Bottom Layer w0.125: v1(145.309,101.641) 145.309,99.674 149.249,95.734 154.518,95.734 v1(154.583,95.799)
  Bottom Layer w0.254: v1@99.526,103.354 99.465,103.293 99.465,97.512 v1@99.719,97.512 ; v1@99.654,83.161 99.719,83.096 99.719,82.272 100.1,81.891 109.625,81.891 110.133,82.399 v1(110.133,89.677) ; v1@106.258,103.862 106.258,106.972 107.339,108.053 123.661,108.053 v1@123.722,107.992
  Bottom Layer w0.4: v1@87.273,102.084 87.273,96.877 88.035,96.115 PWJ1.2@89.432,96.115 95.401,96.115 96.798,97.512 v1@99.719,97.512
  other v1: 99.654,83.161 99.719,97.512 87.273,102.084 99.527,103.354 106.258,103.862 142.264,104.243 123.722,107.992
L1_2: C28.2 L1.2 R4.2 | length 9.3
  Top Layer w0.125: C28.2@101.054,83.161 101.624,83.731 v1(104.418,83.731)
  Bottom Layer w0.125: v1(104.418,83.731) 104.553,83.867 v1@104.553,89.384
  other v1: 104.553,89.384
L2_2: L2.2 R6.2 | length 5.1
  Top Layer w0.125: L2.2@107.974,83.731 109.568,82.136 R6.2@112.419,82.136
LED1_2: LED1.2 R3.1 | length 5.2
  Top Layer w0.125: v1@145.693,93.829 145.986,93.536 LED1.2@145.986,91.797
  Bottom Layer w0.125: v1@145.684,96.877 v1@145.693,93.829
  other v1: 145.693,93.829 145.684,96.877
P0.0_SCLK0: P2.15 U1.H9 | length 46.7
  Top Layer w0.125: v1@148.487,102.846 v1@149.884,102.846 ; v1@156.488,99.036 v1@158.266,99.036 ; v1@170.331,94.972 v1@171.982,94.972
  Bottom Layer w0.1: 139.573,102.719 v1(139.573,106.426)
  Bottom Layer w0.125: 139.573,102.719 143.915,102.719 144.296,102.338 146.074,102.338 146.582,102.846 v1@148.487,102.846 ; v1@149.884,102.846 150.773,102.846 154.583,99.036 v1@156.488,99.036 ; v1@158.266,99.036 159.79,99.036 160.171,98.655 169.061,98.655 170.331,97.385 v1@170.331,94.972 ; v1@171.982,94.972 177.316,94.972 P2.15@177.443,94.845
  other v1: 170.331,94.972 171.982,94.972 156.488,99.036 158.266,99.036 148.487,102.846 149.884,102.846
P0.1_MOSI0: P2.14 U1.H8 | length 47.5
  Top Layer w0.125: v1@156.488,95.226 v1@168.299,95.226 ; v1@169.569,95.607 v1@171.855,95.607
  Bottom Layer w0.1: v1(139.073,106.426) 139.073,104.1 138.835,103.862 138.835,100.941 140.867,98.909 145.312,98.909 148.995,95.226 v1@156.488,95.226
  Bottom Layer w0.125: v1@168.299,95.226 169.188,95.226 v1@169.569,95.607 ; v1@171.855,95.607 174.014,95.607 175.792,97.385 P2.14@177.443,97.385
  other v1: 156.488,95.226 168.299,95.226 169.569,95.607 171.855,95.607
P0.2_MISO0: P2.13 U1.H7 | length 84.5
  Top Layer w0.125: v1@140.359,87.352 v1@140.359,93.829 ; P2.13@177.443,99.925 177.57,100.052 179.475,100.052 180.364,99.163 v1@180.364,90.781
  Bottom Layer w0.1: v1(138.573,106.426) 138.573,103.727 138.327,103.481 138.327,100.687 140.359,98.655 v1@140.359,93.829
  Bottom Layer w0.125: v1@140.359,87.352 144.804,87.352 151.154,81.002 174.522,81.002 175.157,80.367 179.475,80.367 180.364,81.256 v1@180.364,90.781
  other v1: 140.359,87.352 180.364,90.781 140.359,93.829
P0.3_CS0: P2.12 U1.H6 | length 66.5
  Top Layer w0.125: v1@137.692,94.591 137.692,90.527 v1@137.819,90.4 ; v1@155.726,90.4 v1@167.41,90.4 ; v1@170.839,97.512 v1@171.855,97.512
  Bottom Layer w0.1: v1@137.692,94.591 137.692,95.48 137.819,95.734 137.819,104.243 138.073,104.497 v1(138.073,106.426)
  Bottom Layer w0.125: v1@137.819,90.4 v1@155.726,90.4 ; v1@167.41,90.4 170.585,90.4 170.585,94.21 170.839,94.464 v1@170.839,97.512 ; v1@171.855,97.512 173.506,97.512 174.649,98.655 174.649,101.449 175.665,102.465 P2.12@177.443,102.465
  other v1: 137.819,90.4 155.726,90.4 167.41,90.4 137.692,94.591 170.839,97.512 171.855,97.512
P0.4_SCL: P2.11 U1.J5 | length 49.7
  Top Layer w0.1: U1.J5@137.572,105.927 137.572,101.06 139.089,99.544 141.756,99.544 142.137,99.163 145.82,99.163 v1@146.074,99.417
  Top Layer w0.125: v1@146.963,99.417 155.091,99.417 155.98,100.306 155.98,103.227 156.107,103.354 v1@168.172,103.354
  Bottom Layer w0.125: v1@146.074,99.417 v1@146.963,99.417 ; v1@168.172,103.354 175.792,103.354 P2.11@177.443,105.005
  other v1: 146.074,99.417 146.963,99.417 168.172,103.354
